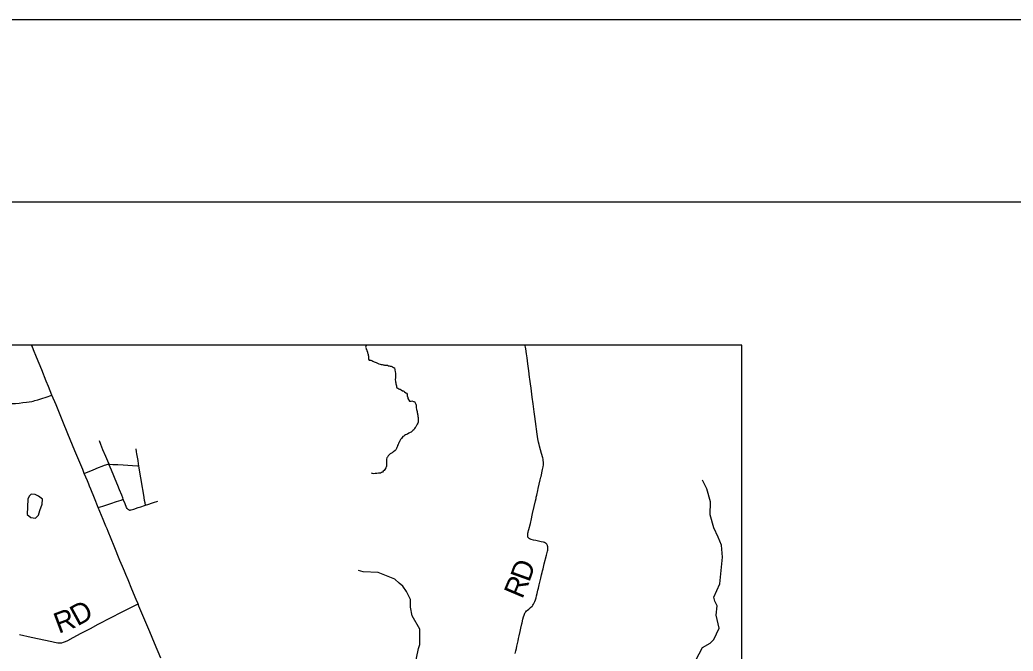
# Model space of a CAD drawing. Extents: x 0 to 34, y 0 to 22.
# Drawn here: x 14.353 to 17.083, y 20.264 to 22 of the extents above; entities that cross this region are included whole.
import ezdxf

# ---------------------------------------------------------------- set-up
doc = ezdxf.new("R2010")
doc.units = 0
for name, color, linetype in [('GM_X_Corporation', 7, 'Continuous'), ('GM_X_Minor_Lake', 7, 'Continuous'), ('GM_X_Minor_River', 7, 'Continuous'), ('GM_X_Township_Road', 7, 'Continuous'), ('GM_X_Township_Road_Text', 7, 'Continuous'), ('GM_X_US_Route', 7, 'Continuous'), ('SH_Border', 7, 'Continuous'), ('SH_Cut_Line', 7, 'Continuous')]:
    doc.layers.add(name, color=color, linetype=linetype)

msp = doc.modelspace()

# ---------------------------------------------------------------- linework, layer by layer
at = {"layer": 'GM_X_Corporation'}
msp.add_lwpolyline([(16.3375, 14.3932), (16.3375, 21.1059), (9.5375, 21.1059), (9.5375, 15.0426), (9.5452, 15.0418), (9.7185, 15.0258), (10.2502, 14.9799), (10.3112, 14.9746), (10.787, 14.9212), (11.3129, 14.8754), (11.3292, 14.8742), (12.1361, 14.7923), (13.6754, 14.6095), (14.714, 14.5341), (15.778, 14.4476), (16.0263, 14.4243)], close=True, dxfattribs=at)
msp.add_lwpolyline([(16.3375, 19.8528), (16.3375, 21.1059), (10.7333, 21.1059)], dxfattribs=at)
at = {"layer": 'GM_X_Minor_Lake'}
for points in [[(14.3724, 20.64), (14.3829, 20.6318), (14.3958, 20.6301), (14.4039, 20.6379), (14.4072, 20.6508), (14.4139, 20.6685), (14.4153, 20.6822), (14.4037, 20.6907), (14.395, 20.6947), (14.384, 20.6956), (14.3782, 20.6908), (14.3747, 20.6821)], [(14.3747, 20.6821), (14.3724, 20.64)]]:
    msp.add_lwpolyline(points, dxfattribs=at)
at = {"layer": 'GM_X_Minor_River'}
for points in [[(15.3046, 21.1059), (15.3045, 21.1051), (15.3037, 21.102), (15.3033, 21.0998), (15.3044, 21.0967), (15.3051, 21.0944), (15.3063, 21.0925), (15.3066, 21.0906), (15.3081, 21.0868), (15.3085, 21.0845), (15.3092, 21.0826), (15.31, 21.0804), (15.3103, 21.0777), (15.3107, 21.075), (15.3114, 21.0712), (15.3114, 21.0686), (15.3114, 21.0667), (15.3132, 21.0644), (15.3174, 21.064), (15.3204, 21.0636), (15.3231, 21.0617), (15.3268, 21.0601), (15.3295, 21.0586), (15.3318, 21.0578), (15.3336, 21.0566), (15.3355, 21.0559), (15.3397, 21.0547), (15.3431, 21.0535)], [(15.3431, 21.0535), (15.3461, 21.0527), (15.3488, 21.0527), (15.351, 21.0519), (15.3529, 21.0515), (15.3548, 21.0511), (15.3567, 21.0511), (15.359, 21.0507), (15.3616, 21.0507), (15.3635, 21.0503), (15.3662, 21.0491), (15.3681, 21.0487), (15.3707, 21.048), (15.373, 21.0476), (15.3749, 21.0468), (15.3772, 21.0464), (15.3798, 21.0445), (15.3828, 21.0433), (15.3839, 21.0376), (15.3842, 21.0327), (15.385, 21.0289), (15.3853, 21.0254), (15.3853, 21.022), (15.3856, 21.0194), (15.3856, 21.0171), (15.3852, 21.0144), (15.3848, 21.0118), (15.3848, 21.0099), (15.3852, 21.0065), (15.3855, 21.0046), (15.3863, 21.0019), (15.3862, 20.9996), (15.3874, 20.997), (15.3877, 20.9935), (15.3885, 20.9909), (15.3892, 20.9886), (15.3915, 20.987), (15.3945, 20.9855), (15.3967, 20.9847), (15.3986, 20.9843), (15.4013, 20.9824), (15.4043, 20.9805), (15.4062, 20.9797), (15.4081, 20.9789), (15.4103, 20.9774), (15.4133, 20.9747), (15.416, 20.9736), (15.4171, 20.9705), (15.4178, 20.9667), (15.4189, 20.9618), (15.4197, 20.9591), (15.4238, 20.9515), (15.4283, 20.9514), (15.4306, 20.9522), (15.4348, 20.951), (15.4374, 20.9506), (15.4408, 20.943), (15.4419, 20.9403), (15.4426, 20.9346), (15.4433, 20.9285), (15.4448, 20.9236), (15.4451, 20.9205), (15.4455, 20.9179), (15.4462, 20.9156), (15.4466, 20.9129), (15.4469, 20.9099), (15.4473, 20.9069), (15.4476, 20.9034), (15.4476, 20.9008), (15.448, 20.8978), (15.4476, 20.894), (15.4464, 20.8909), (15.4452, 20.8887), (15.4414, 20.8815), (15.4395, 20.8789), (15.4379, 20.8762), (15.4356, 20.8728), (15.4333, 20.8713), (15.4299, 20.8679), (15.428, 20.8664), (15.4261, 20.8653), (15.4242, 20.8642), (15.4223, 20.8634), (15.4181, 20.8608), (15.4154, 20.8601), (15.4128, 20.8593), (15.4105, 20.8575), (15.4082, 20.8556), (15.4055, 20.8541), (15.4036, 20.8518), (15.4017, 20.8492), (15.3994, 20.8466), (15.3979, 20.8447), (15.3971, 20.8424), (15.3963, 20.8405), (15.3952, 20.8383), (15.394, 20.836), (15.3932, 20.8341), (15.3925, 20.8322), (15.3909, 20.8299), (15.3905, 20.828)], [(15.3905, 20.828), (15.3898, 20.8258), (15.3886, 20.8239), (15.3882, 20.8216), (15.3863, 20.8182), (15.3844, 20.8163), (15.3802, 20.8122), (15.3779, 20.8111), (15.376, 20.8096), (15.3729, 20.8081), (15.371, 20.8073), (15.3676, 20.8043), (15.3653, 20.8017), (15.363, 20.7979), (15.3615, 20.796), (15.3607, 20.7923), (15.361, 20.7881), (15.3606, 20.785), (15.361, 20.7828), (15.3606, 20.7797), (15.361, 20.7778), (15.3609, 20.7752), (15.3602, 20.7729), (15.3598, 20.7706), (15.359, 20.7684), (15.3563, 20.7638), (15.3544, 20.7612), (15.3517, 20.7589), (15.3494, 20.7567), (15.3471, 20.7552), (15.3441, 20.7541), (15.3414, 20.7541), (15.3388, 20.7534), (15.3342, 20.753), (15.3316, 20.7527), (15.3297, 20.7527), (15.3259, 20.7523), (15.3225, 20.7531), (15.3198, 20.7535)], [(16.2113, 20.2393), (16.2289, 20.2743), (16.2504, 20.2861), (16.2601, 20.2966), (16.2754, 20.3275), (16.2665, 20.3629), (16.2696, 20.3891), (16.2634, 20.4021), (16.2605, 20.4124), (16.2768, 20.4497), (16.2841, 20.5225), (16.2812, 20.556), (16.2721, 20.5778), (16.2608, 20.603), (16.2508, 20.6396), (16.251, 20.675), (16.241, 20.7104), (16.2292, 20.7346)], [(15.4387, 20.2229), (15.4486, 20.2718), (15.4523, 20.2831), (15.4518, 20.3252), (15.4308, 20.3613), (15.4263, 20.3857), (15.4263, 20.4066), (15.416, 20.428), (15.4053, 20.4434), (15.3955, 20.4515), (15.3835, 20.462), (15.3375, 20.4802), (15.2962, 20.4825), (15.2837, 20.4861)]]:
    msp.add_lwpolyline(points, dxfattribs=at)
at = {"layer": 'GM_X_Township_Road'}
for points in [[(15.7146, 20.258), (15.7163, 20.2652), (15.7178, 20.2719), (15.7193, 20.2785), (15.7208, 20.2852), (15.7225, 20.2925), (15.7239, 20.2991), (15.7255, 20.3064), (15.7282, 20.3185), (15.7302, 20.3276), (15.7327, 20.3392), (15.7334, 20.3422), (15.7355, 20.3519), (15.7373, 20.3586), (15.7389, 20.3634), (15.7398, 20.3657), (15.741, 20.3684), (15.7422, 20.3706), (15.7434, 20.3722), (15.7456, 20.3749), (15.7481, 20.3771), (15.7519, 20.3801), (15.7568, 20.3843), (15.7607, 20.3878), (15.7619, 20.3891), (15.7633, 20.3909), (15.7651, 20.3935), (15.7669, 20.3969), (15.7685, 20.4006), (15.7702, 20.4051), (15.7719, 20.4108), (15.7734, 20.4165), (15.7749, 20.4228), (15.777, 20.4319), (15.7784, 20.4378), (15.7806, 20.4469), (15.7824, 20.4542), (15.7848, 20.4648), (15.787, 20.4739), (15.7886, 20.4805), (15.7898, 20.4853), (15.7911, 20.4907), (15.7944, 20.504), (15.8003, 20.5281), (15.803, 20.539), (15.8037, 20.542), (15.8042, 20.5456), (15.8044, 20.5486), (15.8043, 20.551), (15.8036, 20.5538), (15.803, 20.5553), (15.8022, 20.557), (15.8015, 20.5581), (15.8006, 20.5592), (15.7992, 20.5604), (15.7974, 20.5616), (15.7946, 20.5629), (15.792, 20.5637), (15.7854, 20.5652), (15.7824, 20.5659), (15.7783, 20.5668), (15.771, 20.5684), (15.7645, 20.5698), (15.7584, 20.5713), (15.7569, 20.5719), (15.7558, 20.5724), (15.7544, 20.573), (15.7532, 20.5737), (15.7519, 20.5746), (15.7509, 20.5755), (15.75, 20.5765), (15.7494, 20.5777), (15.7491, 20.579), (15.749, 20.5805), (15.749, 20.5829), (15.7491, 20.5858), (15.7494, 20.5886), (15.7501, 20.5917), (15.7511, 20.596), (15.7519, 20.5991), (15.756, 20.6153), (15.7571, 20.6201), (15.7579, 20.6237), (15.7623, 20.6425), (15.7667, 20.6625), (15.7702, 20.6776), (15.7716, 20.6837), (15.7724, 20.6873), (15.7738, 20.6933), (15.7767, 20.7061), (15.7779, 20.7115), (15.7834, 20.7351), (15.7851, 20.7424), (15.7857, 20.7448), (15.7899, 20.7636), (15.7907, 20.7676), (15.7913, 20.7714), (15.7918, 20.7769), (15.792, 20.783), (15.7914, 20.7891), (15.791, 20.7922), (15.7903, 20.7958), (15.787, 20.8079), (15.7814, 20.8281), (15.7801, 20.8329), (15.7787, 20.839), (15.7769, 20.8482), (15.7748, 20.8611), (15.7701, 20.8956), (15.7683, 20.9098), (15.7666, 20.9227), (15.7637, 20.9443), (15.7613, 20.9627), (15.7582, 20.9874), (15.7565, 20.9997), (15.7549, 21.012), (15.7541, 21.0176), (15.7517, 21.0354), (15.7492, 21.0539), (15.747, 21.0705), (15.7455, 21.0822), (15.7437, 21.0951), (15.7427, 21.1), (15.7415, 21.104), (15.7408, 21.1059)], [(14.3191, 20.9453), (14.3288, 20.9452), (14.341, 20.9457), (14.351, 20.9465), (14.3606, 20.9476), (14.3714, 20.9489), (14.3786, 20.9501), (14.3853, 20.9512), (14.3894, 20.9521), (14.3942, 20.9532), (14.4023, 20.9554), (14.4129, 20.9586), (14.4255, 20.9626), (14.4409, 20.9682)], [(14.5977, 20.7781), (14.5969, 20.78), (14.5888, 20.7996), (14.5811, 20.8181), (14.5755, 20.8326), (14.5716, 20.8427)], [(14.6799, 20.774), (14.679, 20.7793), (14.6775, 20.7885), (14.6758, 20.7981), (14.6743, 20.8066), (14.6734, 20.8121), (14.6721, 20.8202)], [(14.5299, 20.7529), (14.5541, 20.7628), (14.5687, 20.7691), (14.5788, 20.7733), (14.5858, 20.776), (14.5889, 20.7769), (14.5915, 20.7775), (14.5946, 20.778), (14.5977, 20.7781)], [(14.5977, 20.7781), (14.6001, 20.7782), (14.608, 20.7778), (14.622, 20.7772), (14.6366, 20.7765), (14.6494, 20.7757), (14.6624, 20.7749), (14.6759, 20.7742), (14.6799, 20.774)], [(14.637, 20.682), (14.6354, 20.6862), (14.6326, 20.6932), (14.6263, 20.7082), (14.6216, 20.7199), (14.6147, 20.7371), (14.6109, 20.7462), (14.6043, 20.7621), (14.601, 20.7704), (14.5977, 20.7781)], [(14.6981, 20.6657), (14.6969, 20.6721), (14.6957, 20.6788), (14.6945, 20.6868), (14.6918, 20.704), (14.6893, 20.7187), (14.6863, 20.7364), (14.6847, 20.7456), (14.6809, 20.7683), (14.6799, 20.774)], [(14.5684, 20.6591), (14.5744, 20.6611), (14.5804, 20.6631), (14.6032, 20.6706), (14.6185, 20.6758), (14.6309, 20.6799), (14.637, 20.682)], [(14.6542, 20.6524), (14.6522, 20.6529), (14.6512, 20.6533), (14.6502, 20.6539), (14.6492, 20.6548), (14.6485, 20.6557), (14.6476, 20.6569), (14.6463, 20.6592), (14.6449, 20.6623), (14.6431, 20.6666), (14.6419, 20.6695), (14.6379, 20.6799), (14.637, 20.682)], [(14.6981, 20.6657), (14.7072, 20.6688), (14.7142, 20.6712), (14.7201, 20.6732), (14.7316, 20.6771)], [(14.6542, 20.6524), (14.6563, 20.6524), (14.6579, 20.6526), (14.6588, 20.6528), (14.666, 20.655), (14.6784, 20.659), (14.6855, 20.6613), (14.6949, 20.6646), (14.6981, 20.6657)], [(14.3518, 20.3098), (14.384, 20.3031), (14.4405, 20.291), (14.4484, 20.2892), (14.457, 20.2877), (14.462, 20.2873), (14.4678, 20.2876), (14.4727, 20.2887), (14.4781, 20.2906), (14.4843, 20.2935), (14.4991, 20.3017), (14.5214, 20.3138), (14.5467, 20.3271), (14.5681, 20.3384), (14.6033, 20.357), (14.632, 20.3718), (14.6503, 20.3809), (14.6581, 20.3848), (14.6636, 20.3874), (14.6703, 20.3906), (14.6777, 20.3941)]]:
    msp.add_lwpolyline(points, dxfattribs=at)
at = {"layer": 'GM_X_US_Route'}
for points in [[(14.3904, 21.0924), (14.3862, 21.1028), (14.385, 21.1059)], [(14.7401, 20.2448), (14.7225, 20.2866), (14.7099, 20.3171), (14.6934, 20.356), (14.6801, 20.3881), (14.6777, 20.3941), (14.6726, 20.4065), (14.6608, 20.4345), (14.6501, 20.4604), (14.6442, 20.4748), (14.6402, 20.4845), (14.6349, 20.4971), (14.628, 20.5137), (14.6117, 20.5534), (14.5952, 20.5936), (14.5924, 20.6006), (14.5894, 20.608), (14.5821, 20.6259), (14.5684, 20.6591), (14.5681, 20.6597), (14.5578, 20.6851), (14.5476, 20.7098), (14.5441, 20.7184), (14.542, 20.7235), (14.5385, 20.7322), (14.5299, 20.7529), (14.5256, 20.7635), (14.5177, 20.7827), (14.5043, 20.8152), (14.4849, 20.8621), (14.4712, 20.8954), (14.4523, 20.9413), (14.4409, 20.9682), (14.4312, 20.9918), (14.425, 21.007), (14.4127, 21.0376), (14.3983, 21.0727), (14.3904, 21.0924)]]:
    msp.add_lwpolyline(points, dxfattribs=at)
at = {"layer": 'SH_Border'}
msp.add_lwpolyline([(1.5, 21.5), (33.5, 21.5), (33.5, 0.5), (1.5, 0.5)], close=True, dxfattribs=at)
at = {"layer": 'SH_Cut_Line'}
msp.add_lwpolyline([(0, 0), (34, 0), (34, 22), (0, 22)], close=True, dxfattribs=at)

# ---------------------------------------------------------------- texts
at = {"layer": 'GM_X_Township_Road_Text'}
for s, rotation, p in [('D', 70.2469, (15.753, 20.452)), ('R', 67.1396, (15.7337, 20.4059)), ('D', 28.7349, (14.5109, 20.332)), ('R', 20.504, (14.4593, 20.312))]:
    msp.add_text(s, height=0.0568, rotation=rotation, dxfattribs=at).set_placement(p)

doc.saveas('drawing.dxf')
